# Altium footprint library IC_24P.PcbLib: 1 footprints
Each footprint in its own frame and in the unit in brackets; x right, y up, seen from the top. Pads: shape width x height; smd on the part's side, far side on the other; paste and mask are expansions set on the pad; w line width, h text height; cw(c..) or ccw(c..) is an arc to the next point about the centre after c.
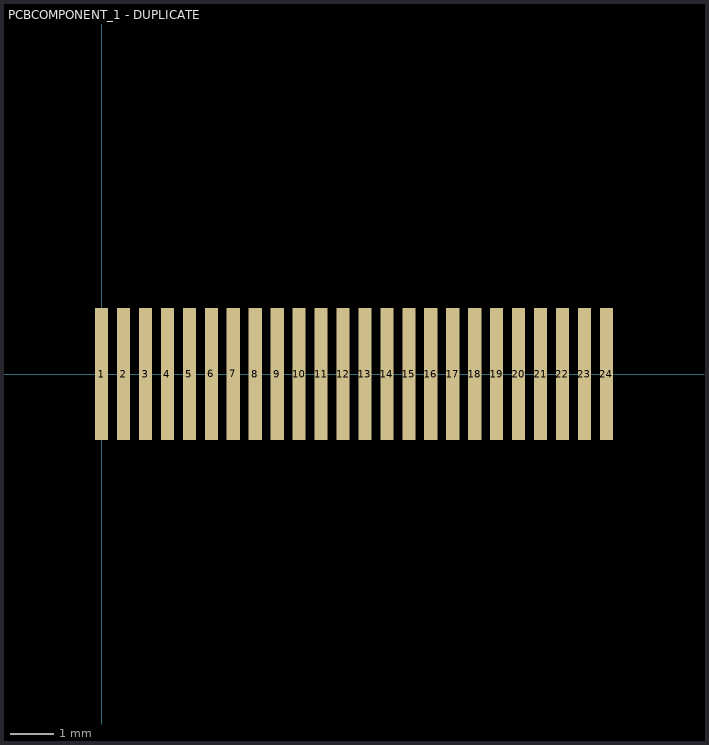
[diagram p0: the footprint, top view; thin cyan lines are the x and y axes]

## PCBCOMPONENT_1 - DUPLICATE [mm]
pads (24):
  rect 0.3x3 smd: 1(0,0) 2(0.5,0) 3(1,0) 4(1.5,0) 5(2,0) 6(2.5,0) 7(3,0) 8(3.5,0) 9(4,0) 10(4.5,0) 11(5,0) 12(5.5,0) 13(6,0) 14(6.5,0) 15(7,0) 16(7.5,0) 17(8,0) 18(8.5,0) 19(9,0) 20(9.5,0) 21(10,0) 22(10.5,0) 23(11,0) 24(11.5,0)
